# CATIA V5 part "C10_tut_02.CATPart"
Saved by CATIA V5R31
Part number: Part1
Bounding box of the stored display mesh (mm): x -105 to 105, y -154.964 to 550, z -23.252 to 23.251
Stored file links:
  D:\PROJECTS\Project 2021\US EDITION\CATIA V5 6R 2021\Resources\Tutorial Files\c10_catia_v5_6r2021_tut\C10_tut_02.CATPart
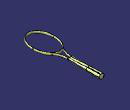
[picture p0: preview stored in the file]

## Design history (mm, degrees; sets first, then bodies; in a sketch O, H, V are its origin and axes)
Body1 (main body)
  Sketch1 on xy-plane, origin (0, 0, 0), H (1, 0, 0), V (0, 1, 0)
    ellipse A1 centre (0, 0) semi-axes 100, 150 rotation 0
    point P1 (100, 0)
    point P2 (-100, 0)
    "Radius" A1 = 100
    "Radius" A1 = 150
    "Radius" A1 = 100 (reference)
    coincidence: P1 H, A1 P1, P2 A1, P2 H
    perpendicularity: A1 V
  Sketch2 on zx-plane, origin (0, 0, 0), H (-1, 0, 0), V (0, 0, 1)
    point P1 (100, 0)
    ellipse A1 centre (100, 0) semi-axes 10, 5 rotation 270
    reference projected point E1 (100, 0) from Sketch1.P2
    "Radius" A1 = 10
    "Radius" A1 = 5
    coincidence: P1 H, P1 E1
    vertical: A1 V
  Sweep1: type Unspec, Profile Sketch2, Guide Sketch1.A1
  Sketch3 on xy-plane, origin (0, 0, 0), H (1, 0, 0), V (0, 1, 0)
    line L1 (15, 245) -> (15, 250)
    point P2 (15, 250)
    arc A1 centre (215, 245) radius 200 from (15, 245) to (55, 125) ccw
    point P4 (55, 125)
    distance L1 V = 15
    distance P2 H = 250
    radius A1 = 200
    distance P4 V = 55
    distance P4 H = 125
    tangency: L1 A1
  Plane1: type Normal, Curve Sketch3, RefPoint Sketch3.P2, Ratio 0
  Sketch4 on Plane1, origin (0, 250, 0), H (1, 0, 0), V (0, 0, 1)
    point P1 (15, 0)
    ellipse A1 centre (15, 0) semi-axes 8.75, 4.5 rotation 270
    reference projected point E1 (15, 0) from Sketch3.P2
    "Radius" A1 = 8.75
    "Radius" A1 = 4.5
    coincidence: P1 H, P1 E1
  Sweep2: type Unspec, Profile Sketch4, Guide Sketch3
  Symmetry1: ToTransfor Sweep2, Reference yz-plane
  Trim1: Trimmed (Symmetry1; Sweep1)
  Trim2: Trimmed (Sweep2; Trim1)
  Sketch5 on Plane1, origin (0, 250, 0), H (1, 0, 0), V (0, 0, 1)
    projected curve E1 from edge of Sweep2
    projected curve E2 from edge of Sweep2
    projected curve E3 from edge of Symmetry1
    projected curve E4 from edge of Symmetry1
    line L1 (11.75, 6.052) -> (-11.75, 6.052)
    point P1 (11.75, 6.052)
    point P2 (-11.75, 6.052)
    reference intersected line E5 through (0, 0) direction (-1, 0) from xy-plane
    point P5 (-11.75, -6.052)
    point P6 (11.75, -6.052)
    line L2 (11.75, -6.052) -> (-11.75, -6.052)
    point P7 (-11.75, -6.052)
    point P8 (11.75, -6.052)
    length L1 = 23.5
    coincidence: P1 E1, P2 E3, L2 P7, L2 P8
    horizontal: L1 H
    symmetry: P2 P5 E5, P1 P6 E5, L1 L2 E5
  Plane2: type Offset, RefPlane zx-plane, Offset 425
  Sketch6 on Plane2, origin (0, 425, 0), H (-1, 0, 0), V (0, 0, 1)
    ellipse A1 centre (0, 0) semi-axes 22.5, 20 rotation 0
    point P1 (22.5, 0)
    point P2 (-11.75, 17.0562)
    point P3 (11.75, 17.0562)
    point P4 (11.75, -17.0562)
    point P5 (-11.75, -17.0562)
    "Radius" A1 = 22.5
    "Radius" A1 = 20
    distance P2 P3 = 23.5
    distance P2 V = 11.75
    distance P5 V = 11.75
    distance P4 P5 = 23.5
    distance P3 P4 = 34.1124
    coincidence: P1 H, A1 P1, P2 A1, P3 A1, P4 A1, P5 A1
  Loft1: Sections (Sketch5; Sketch6.A1), SectionCouplingPoints ({coupling CouplingPoints (vertex [element of Sketch5 | element of Sketch5]; Sketch6.P2)}; {coupling CouplingPoints (vertex [element of Sketch5 | element of Sketch5]; Sketch6.P5)}; {coupling CouplingPoints (vertex [element of Sketch5 | element of Sketch5]; Sketch6.P3)}; {coupling CouplingPoints (vertex [element of Sketch5 | element of Sketch5]; Sketch6.P4)})
  Plane3: type Offset, RefPlane zx-plane, Offset 550
  Sketch7 on Plane3, origin (0, 550, 0), H (-1, 0, 0), V (0, 0, 1)
    circle A1 centre (0, 0) radius 22.5
    radius A1 = 22.5
  Blend1: StartLimit {blendlimit Curve Sketch6.A1, Point {extremum Reference Sketch6.A1, Direction (1, 2, 3)}, Support Loft1}, EndLimit {blendlimit Curve Sketch7, Point {extremum Reference Sketch7, Direction (1, 2, 3)}}
  Fill1: Boundary edge of Blend1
